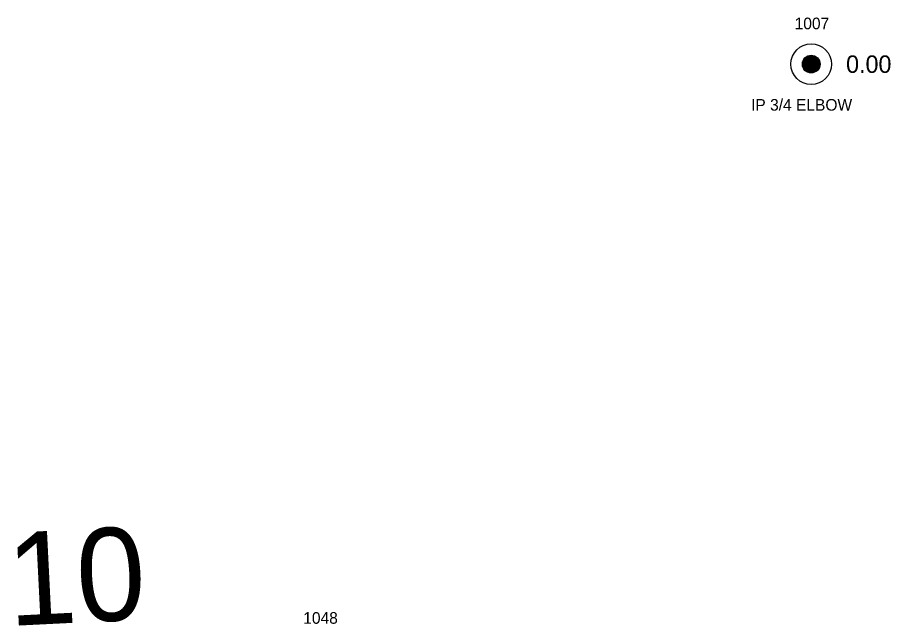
# Model space of a CAD drawing. Extents: x 1539151 to 1541799, y 1198646 to 1201165.
# Drawn here: x 1539383 to 1539458.2, y 1199458 to 1199510.3 of the extents above; entities that cross this region are included whole.
import ezdxf

# ---------------------------------------------------------------- set-up
doc = ezdxf.new("R2010")
doc.units = 0
for name, color, linetype in [('RD_EX_DV_Prop_txCode', 7, 'Continuous'), ('RD_EX_DV_PropPin', 7, 'Continuous'), ('RD_EX_Road_txCode', 7, 'Continuous'), ('RD_EX_TX_DV_Prop_ELEV', 7, 'Continuous'), ('RD_HC_TX_Sta50', 7, 'Continuous'), ('RD_SMD_Locator', 7, 'Continuous')]:
    doc.layers.add(name, color=color, linetype=linetype)

msp = doc.modelspace()

# ---------------------------------------------------------------- linework, layer by layer
at = {"layer": 'RD_EX_DV_PropPin'}
for p, q in [((1539450.596, 1199506.104), (1539450.596, 1199506.497)), ((1539450.631, 1199506.003), (1539450.631, 1199506.599)), ((1539450.666, 1199505.931), (1539450.666, 1199506.67)), ((1539450.701, 1199505.874), (1539450.701, 1199506.727)), ((1539450.736, 1199505.826), (1539450.736, 1199506.775)), ((1539450.771, 1199505.786), (1539450.771, 1199506.816)), ((1539450.806, 1199505.75), (1539450.806, 1199506.851)), ((1539450.841, 1199505.718), (1539450.841, 1199506.883)), ((1539450.876, 1199505.691), (1539450.876, 1199506.91)), ((1539450.911, 1199505.666), (1539450.911, 1199506.935)), ((1539450.946, 1199505.644), (1539450.946, 1199506.957)), ((1539450.981, 1199505.625), (1539450.981, 1199506.976)), ((1539451.016, 1199505.608), (1539451.016, 1199506.993)), ((1539451.051, 1199505.593), (1539451.051, 1199507.008)), ((1539451.086, 1199505.58), (1539451.086, 1199507.021)), ((1539451.121, 1199505.569), (1539451.121, 1199507.032)), ((1539451.157, 1199505.56), (1539451.157, 1199507.041)), ((1539451.192, 1199505.553), (1539451.192, 1199507.049)), ((1539451.227, 1199505.547), (1539451.227, 1199507.054)), ((1539451.262, 1199505.543), (1539451.262, 1199507.058)), ((1539451.297, 1199505.54), (1539451.297, 1199507.061)), ((1539451.332, 1199505.54), (1539451.332, 1199507.062)), ((1539451.367, 1199505.54), (1539451.367, 1199507.061)), ((1539451.402, 1199505.543), (1539451.402, 1199507.058)), ((1539451.437, 1199505.547), (1539451.437, 1199507.054)), ((1539451.472, 1199505.553), (1539451.472, 1199507.049)), ((1539451.507, 1199505.56), (1539451.507, 1199507.041)), ((1539451.542, 1199505.569), (1539451.542, 1199507.032)), ((1539451.577, 1199505.58), (1539451.577, 1199507.021)), ((1539451.612, 1199505.593), (1539451.612, 1199507.008)), ((1539451.647, 1199505.608), (1539451.647, 1199506.993)), ((1539451.682, 1199505.625), (1539451.682, 1199506.976)), ((1539451.717, 1199505.644), (1539451.717, 1199506.957)), ((1539451.752, 1199505.666), (1539451.752, 1199506.935)), ((1539451.787, 1199505.691), (1539451.787, 1199506.91)), ((1539451.822, 1199505.718), (1539451.822, 1199506.883)), ((1539451.857, 1199505.75), (1539451.857, 1199506.851)), ((1539451.892, 1199505.786), (1539451.892, 1199506.816)), ((1539451.927, 1199505.826), (1539451.927, 1199506.775)), ((1539451.962, 1199505.874), (1539451.962, 1199506.727)), ((1539451.997, 1199505.931), (1539451.997, 1199506.67)), ((1539452.032, 1199506.003), (1539452.032, 1199506.599)), ((1539452.067, 1199506.104), (1539452.067, 1199506.497))]:
    msp.add_line(p, q, dxfattribs=at)
for radius in [1.75, 0.761]:
    msp.add_circle((1539451.332, 1199506.301), radius, dxfattribs=at)
at = {"layer": 'RD_SMD_Locator'}
msp.add_circle((1539451.332, 1199506.301), 0.15, dxfattribs=at)

# ---------------------------------------------------------------- texts
at = {"layer": 'RD_EX_DV_Prop_txCode'}
for s, p in [('1007', (1539449.906, 1199509.301)), ('IP 3/4 ELBOW', (1539446.158, 1199502.301))]:
    msp.add_text(s, height=1, dxfattribs=at).set_placement(p)
at = {"layer": 'RD_EX_Road_txCode'}
msp.add_text('1048', height=1, dxfattribs=at).set_placement((1539407.631, 1199458.172))
at = {"layer": 'RD_EX_TX_DV_Prop_ELEV'}
msp.add_text('0.00', height=1.5, dxfattribs=at).set_placement((1539454.332, 1199505.551))
at = {"layer": 'RD_HC_TX_Sta50'}
msp.add_text('10', height=8, rotation=2.86187, dxfattribs=at).set_placement((1539382.35, 1199457.98))

doc.saveas('drawing.dxf')
